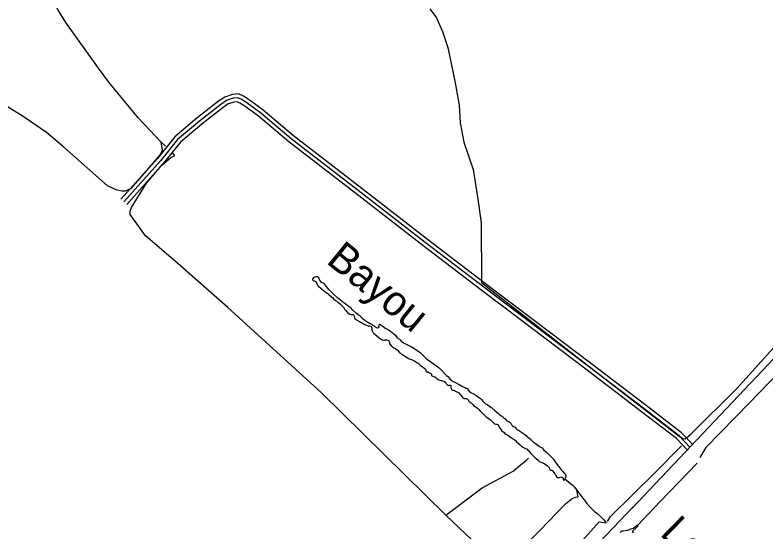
# Model space of a CAD drawing. Extents: x 3161665 to 3199565, y 885729 to 911164.
# Drawn here: x 3166281 to 3169197, y 904720 to 906728 of the extents above; entities that cross this region are included whole.
import ezdxf

# ---------------------------------------------------------------- set-up
doc = ezdxf.new("R2010")
doc.units = 0
for name, color, linetype in [('V-RIVR-IDEN', 7, 'Continuous'), ('V-ROAD-CNTR', 7, 'Continuous'), ('V-TOPO-SHOR', 7, 'Continuous')]:
    doc.layers.add(name, color=color, linetype=linetype)

msp = doc.modelspace()

# ---------------------------------------------------------------- linework, layer by layer
at = {"layer": 'V-ROAD-CNTR'}
for points in [[(3170298.7, 906515.6), (3169343.1, 905515.1), (3168677.2, 904811.3)], [(3167186.6, 906400.7), (3167169.1, 906412.2), (3167149.6, 906421.2), (3167126, 906419.3), (3167095.8, 906409.3), (3167081.9, 906399.9)], [(3167081.9, 906399.9), (3167071.4, 906392.6), (3166987.8, 906327), (3166901.8, 906255.1), (3166834.3, 906171), (3166692.6, 906012.1)], [(3168902.4, 905049.3), (3168859.9, 905093.7), (3168723.7, 905199.1), (3168507.4, 905363.7), (3168188, 905605), (3167873.6, 905844), (3167614.2, 906046.6), (3167353.7, 906246.4), (3167236.2, 906347), (3167187, 906382.4), (3167161.8, 906399.1), (3167146.9, 906406), (3167129, 906404.5), (3167102.5, 906395.8), (3167080.2, 906380.5), (3166997.3, 906315.3), (3166912.5, 906244.5), (3166845.8, 906161.3), (3166703.8, 906002.1)], [(3167167.5, 906377.3), (3167154.5, 906385.9), (3167144.2, 906390.7), (3167132, 906389.7), (3167109.2, 906382.2), (3167098, 906374.5)], [(3168108.6, 905684.2), (3167882.7, 905855.9), (3167623.4, 906058.4), (3167363.2, 906258.1), (3167245.5, 906358.8), (3167195.5, 906394.8), (3167188.5, 906399.4)], [(3167098, 906374.5), (3167089.1, 906368.4), (3167006.7, 906303.7), (3166923.3, 906234), (3166857.2, 906151.6), (3166715, 905992.1)], [(3168090.6, 905660.2), (3167864.4, 905832.1), (3167605.1, 906034.7), (3167344.3, 906234.7), (3167227, 906335.2), (3167178.5, 906370.1), (3167167.5, 906377.3)], [(3168891.6, 905038.9), (3168849.8, 905082.5), (3168714.6, 905187.2), (3168498.3, 905351.7), (3168178.9, 905593), (3168090.6, 905660.2)], [(3168913.3, 905059.7), (3168869.9, 905104.9), (3168732.8, 905211), (3168516.4, 905375.6), (3168197.1, 905616.9), (3168108.6, 905684.2)], [(3168682.8, 904817.2), (3168682.1, 904817.3), (3168500.2, 904627.3), (3168260.8, 904368.7), (3167998.1, 904096.6), (3167913.2, 904008.1), (3167816, 903915.2), (3167746.2, 903847.5), (3167631.8, 903748), (3167456.1, 903609.1), (3167355.1, 903531.9), (3167229.6, 903443.7), (3167105.2, 903362.7), (3166973.6, 903283.3), (3166847.9, 903211.6), (3166848.1, 903211.9), (3166676.1, 903125.4), (3166497, 903041.3), (3166200.2, 902917.8), (3166006.1, 902838.5), (3165919.5, 902802.7)]]:
    msp.add_lwpolyline(points, dxfattribs=at)
at = {"layer": 'V-TOPO-SHOR'}
for points in [[(3166847.9, 906234.9), (3166760.3, 906327.2), (3166645, 906466.6), (3166605.5, 906521.3), (3166478.4, 906698.3), (3166447.5, 906748.6), (3166400.6, 906843), (3166306.9, 907093.7), (3166238.8, 907250.1)], [(3167891.8, 906751.9), (3167918.5, 906716.5), (3167940.8, 906664), (3167962.1, 906601.8), (3167990.7, 906463.7), (3168005.5, 906378), (3168009.6, 906309.5), (3168024.5, 906234.5), (3168060.6, 906127.4), (3168078.6, 906012.8), (3168091.2, 905920.7), (3168092.9, 905689.4), (3168452, 905408.1), (3168860.2, 905092.5), (3168876.3, 905082.8), (3168883.8, 905081.7), (3168906.3, 905099.8), (3169084.4, 905277.2), (3169274.4, 905487.7)], [(3166866, 906218.8), (3166847.9, 906234.9), (3166852.1, 906202.8), (3166846.7, 906186.8), (3166809.1, 906142.9), (3166729.7, 906053.2), (3166709.3, 906043.6), (3166696.5, 906043.6), (3166674, 906049), (3166639.8, 906064.1), (3166471, 906214.4), (3166403.6, 906271.2), (3166309.6, 906335.7), (3166153.5, 906430.2), (3166056.2, 906495.8), (3165966.4, 906555.9), (3165923.6, 906588.1)], [(3170196.9, 906325), (3170037, 906157.3), (3169780.6, 905889.1), (3169471.5, 905570.7), (3169134.6, 905222.5), (3168964, 905048.3), (3168940.4, 905009.8)], [(3167953.8, 904785), (3167472, 905260.4), (3167107.7, 905592), (3166904.7, 905770.2), (3166788.2, 905870), (3166756.2, 905915), (3166728.4, 905953.6), (3166728.4, 905966.5), (3166733.8, 905980.4), (3166791.8, 906074.5), (3166849.8, 906142.9), (3166886.3, 906174.9), (3166902.3, 906182.4), (3166891.7, 906195.2)], [(3167701.9, 905523.9), (3167699.8, 905525.2), (3167696.4, 905526.2), (3167693.7, 905524.4), (3167693.1, 905520.7), (3167693.9, 905516.1), (3167692.4, 905512.6), (3167688.8, 905511.2), (3167685.1, 905513.1), (3167677.8, 905518.4), (3167674.8, 905520.2), (3167672, 905522.5), (3167669.1, 905524.3), (3167661.8, 905528.2), (3167658, 905529.7), (3167651.7, 905533.2), (3167648.3, 905535.4), (3167644.6, 905537.5), (3167641, 905539.9), (3167631.1, 905548.9), (3167626.4, 905552.6), (3167621, 905557.5), (3167612.9, 905564.3), (3167610.7, 905566.5), (3167606.6, 905570.2), (3167592.3, 905582.4), (3167584.8, 905590), (3167579.5, 905594.3), (3167575.7, 905597.4), (3167569, 905602.3), (3167566.2, 905604.7), (3167558.7, 905609.9), (3167554.6, 905613.1), (3167550, 905616.2), (3167545.9, 905618.9), (3167539.7, 905624), (3167535.4, 905628.3), (3167532, 905631.1), (3167518.8, 905642.8), (3167510.8, 905651.4), (3167503.1, 905658.9), (3167500.1, 905662.2), (3167494.4, 905668.7), (3167487.4, 905678.5), (3167482.1, 905683.4), (3167477.8, 905686.1), (3167471.6, 905689.4), (3167467.1, 905694.1), (3167464.5, 905698.3), (3167462.5, 905703.4), (3167461.1, 905707.5), (3167458.5, 905710.2), (3167455.6, 905711.2), (3167451.6, 905711.4), (3167445.5, 905710), (3167439.2, 905705.2), (3167436.5, 905701.7), (3167436.1, 905698.7), (3167438.5, 905696.9), (3167446.4, 905694), (3167449.6, 905691.3), (3167452.9, 905685.2), (3167455.1, 905681.5), (3167456.7, 905677.9), (3167458.7, 905675), (3167462.7, 905671.5), (3167469, 905667.2), (3167472, 905664.6), (3167479.5, 905657.2), (3167483, 905654.8), (3167485.8, 905652.3), (3167496.1, 905645.6), (3167500.2, 905642.5), (3167510.7, 905633.5), (3167514.9, 905629.4), (3167517.9, 905625.9), (3167525.8, 905618.8), (3167530.5, 905615.9), (3167534.1, 905613.2), (3167538, 905610.8), (3167545.4, 905604.2), (3167550.7, 905599.3), (3167556.4, 905592.6), (3167561.4, 905585.3), (3167563.4, 905582.6), (3167567.2, 905579.1), (3167574.3, 905570.4), (3167577.3, 905567.9), (3167581.6, 905565.4), (3167586.9, 905564.2), (3167590.3, 905565.2), (3167594.2, 905564.6), (3167597.4, 905561.9), (3167598.8, 905558.8), (3167599.2, 905551.1), (3167601, 905548.7), (3167607.9, 905543.6), (3167618.6, 905537.8), (3167625.3, 905533.5), (3167634.2, 905528.2), (3167642.5, 905524.1)], [(3167642.5, 905524.1), (3167646.8, 905522.6), (3167652.4, 905521.2), (3167657.5, 905520.7), (3167664.2, 905519.7), (3167666.8, 905513.2), (3167667.4, 905509.5), (3167667.2, 905505.2), (3167668, 905501), (3167669.2, 905498.1), (3167672, 905493.2), (3167674.6, 905491), (3167678.7, 905488.7), (3167686.6, 905482), (3167694.7, 905475.8), (3167700.5, 905470.3), (3167703.8, 905467.7), (3167707.4, 905465.6), (3167711.9, 905464.6), (3167715.7, 905464.3), (3167718.6, 905465.7), (3167721.8, 905466.5), (3167724.9, 905466.1), (3167728.7, 905465.3), (3167731.4, 905463.4), (3167733.8, 905460.4), (3167736, 905452.6), (3167741.6, 905443.5), (3167744, 905440.4), (3167746.7, 905438.4), (3167752.1, 905435.3), (3167755.2, 905434.3), (3167759, 905432.2), (3167766.3, 905425.9), (3167774.8, 905416.7), (3167777.8, 905414.4), (3167782.7, 905411.1), (3167787.5, 905408.3), (3167803.5, 905397.2), (3167812.4, 905392.5), (3167823.2, 905388), (3167830.1, 905385.7), (3167837.6, 905381.4), (3167841.2, 905378.5), (3167846.5, 905375), (3167851.7, 905370.7), (3167854.3, 905368.3), (3167863.9, 905361.7), (3167867.3, 905359.1), (3167872.8, 905355.4), (3167875, 905352.9), (3167876.6, 905348.9), (3167876.8, 905345.6), (3167879.8, 905341.7), (3167882.8, 905341.3), (3167886.9, 905340.3), (3167891.1, 905338.2), (3167895.8, 905335.1), (3167898, 905332.9), (3167898.8, 905329), (3167900.4, 905326), (3167903.7, 905324.5), (3167907.1, 905323.9), (3167911.6, 905322.3), (3167916.6, 905319.2), (3167919.9, 905316.1), (3167923.7, 905313.1), (3167927.2, 905311.4), (3167937.9, 905308.3), (3167945.8, 905305.4), (3167948.6, 905303.8), (3167952.1, 905300.9), (3167954.1, 905298.7), (3167956.9, 905294), (3167959.3, 905291.3), (3167964, 905289.1), (3167966.9, 905290.1), (3167971.3, 905290.6), (3167974, 905288.8), (3167973.9, 905284.5), (3167973.7, 905281.3), (3167974.5, 905277.2), (3167977.3, 905272.3), (3167980.4, 905270.9), (3167984, 905270.7), (3167987.7, 905269), (3167991.3, 905266.4), (3168004.1, 905260.2), (3168007.9, 905257.1), (3168010.1, 905254.5), (3168017.2, 905245.1), (3168020.8, 905241.8), (3168025.3, 905238.7), (3168033.6, 905237.9), (3168036.6, 905236.9), (3168041.1, 905233), (3168042.9, 905229.3), (3168045.9, 905225), (3168049, 905223), (3168053, 905220.9), (3168055.8, 905218.5)], [(3167701.9, 905523.9), (3167708, 905519.6), (3167710.8, 905518), (3167715.7, 905513.5), (3167718, 905512.7)], [(3167718, 905512.7), (3167721.5, 905510), (3167729, 905506.5), (3167733.8, 905503.6), (3167739.3, 905499.6), (3167745.3, 905494.6), (3167748.2, 905492), (3167751, 905490.1), (3167756.9, 905485), (3167759.7, 905481.8), (3167765.5, 905473.6), (3167773.8, 905469.3), (3167777.1, 905466), (3167781.1, 905460.9), (3167784.3, 905457.9), (3167789.8, 905454.6), (3167792.7, 905453.5), (3167795.5, 905451.7), (3167804.8, 905446.6), (3167818.8, 905440.2), (3167821.6, 905438.6), (3167830.7, 905432.4), (3167834, 905430.8), (3167842.3, 905425.2), (3167849.3, 905420.3), (3167856, 905415.4), (3167860.1, 905411.9), (3167868.3, 905403), (3167880.5, 905391.7), (3167899.1, 905379), (3167907, 905373.1), (3167914.7, 905367.7), (3167922.6, 905361.4), (3167929.2, 905356.5), (3167932.5, 905353.8), (3167941.6, 905345.1), (3167951.9, 905333.2), (3167957.3, 905328.1), (3167961.6, 905323.6), (3167968, 905316.3), (3167979.3, 905307.5), (3167983, 905305), (3167989.3, 905302.1), (3167991.9, 905300.5), (3168006.3, 905292.3), (3168019, 905285.5), (3168022.5, 905283.5), (3168028.2, 905280.6), (3168032, 905278.9), (3168035.2, 905277.9), (3168038.1, 905276.1), (3168041.3, 905272), (3168045.3, 905266.5), (3168050, 905263), (3168053.4, 905260.1), (3168056.7, 905258.5), (3168065, 905254.8), (3168068.8, 905252.3), (3168075.9, 905247.2), (3168080.8, 905243.9), (3168088.5, 905238.2), (3168093.9, 905233.3), (3168096.7, 905229.8), (3168102.8, 905223.1), (3168105.4, 905220.6), (3168108.5, 905218.2), (3168114.5, 905214.5), (3168119.4, 905211.6), (3168122.8, 905209.4), (3168130.1, 905203.8), (3168132.9, 905201.6), (3168145.7, 905190.1), (3168158.8, 905179.7), (3168162.7, 905176.2), (3168169.1, 905171.5), (3168172.8, 905169.3), (3168176.6, 905166.4), (3168180.1, 905162.9), (3168184.3, 905159.2), (3168191.6, 905152.1), (3168194.6, 905150.2), (3168197.5, 905149.2), (3168200.5, 905147.6), (3168203.7, 905145.3), (3168206.2, 905142.3), (3168208.8, 905137.4), (3168210.6, 905134.7), (3168213.4, 905132.3), (3168217.5, 905130), (3168224.6, 905126.5), (3168226.2, 905123), (3168228.6, 905120), (3168234.7, 905115.9), (3168240.7, 905112.2), (3168243.8, 905110.6), (3168246.6, 905108.1), (3168249, 905106.3), (3168253.3, 905103.8), (3168257.3, 905100.7), (3168264.8, 905095.4), (3168270.1, 905090.1)], [(3168055.8, 905218.5), (3168058.7, 905214.8), (3168061.5, 905211.7), (3168068.4, 905206.8), (3168077.1, 905200.9), (3168079.7, 905198.4), (3168083.1, 905194.7), (3168087.6, 905189.6), (3168090, 905187.4), (3168092.4, 905184.7), (3168101.5, 905176.6), (3168109.4, 905168), (3168118.1, 905161.8), (3168128.4, 905153.7), (3168138.9, 905143.6), (3168143.4, 905140), (3168148, 905138.3), (3168152.1, 905138.3), (3168155.7, 905137.7), (3168157.6, 905135.2), (3168158.8, 905132.2), (3168161.2, 905128.7), (3168164.4, 905123), (3168169, 905116.1), (3168171.7, 905112.8), (3168180.2, 905105.8), (3168183.4, 905102.8), (3168187.4, 905099.9), (3168190.9, 905097.9), (3168194.3, 905096.4), (3168198, 905094.4), (3168204.6, 905090.1), (3168223.5, 905076.1), (3168226.1, 905073.7), (3168228.9, 905070.6), (3168235.8, 905064.3), (3168243.1, 905057.9), (3168246.7, 905054.3), (3168253.2, 905049.2), (3168263.9, 905044.8), (3168269.8, 905041.1), (3168273.2, 905038.1), (3168276.3, 905034.8), (3168278.7, 905031.7), (3168284.1, 905024.2), (3168288, 905021.3), (3168291.4, 905018.5), (3168301.7, 905008.5), (3168304.7, 905005.8), (3168312.2, 904998.2), (3168314.8, 904995.8), (3168317.3, 904993.9), (3168320.1, 904992.5), (3168323.5, 904991.5), (3168330.8, 904988.8), (3168334.1, 904987.2), (3168344, 904981.2), (3168349.3, 904976.9), (3168352.7, 904973.2), (3168354.9, 904969.8), (3168356.9, 904965.7), (3168358.7, 904962.6), (3168362, 904960.4), (3168365.4, 904960.4), (3168368.7, 904957.9), (3168378.1, 904946.3), (3168380, 904943.6), (3168384.2, 904934.7), (3168387.4, 904931.4), (3168390.9, 904930.4), (3168394.9, 904931.6), (3168401, 904934), (3168404.3, 904932.9), (3168407.3, 904931.5), (3168409.3, 904928.6), (3168409.7, 904925), (3168411.7, 904921.7), (3168414.8, 904922.7), (3168416.6, 904926.6)], [(3168270.1, 905090.1), (3168272.9, 905088.3), (3168281.4, 905081.3), (3168295.5, 905067.4), (3168298, 905065.6), (3168306.1, 905060.4), (3168318.4, 905052), (3168323.3, 905049.8), (3168328.1, 905046.9), (3168332, 905041.8), (3168335.2, 905038.3), (3168339.4, 905034.3), (3168345.3, 905029.5), (3168349.7, 905025.7), (3168359.8, 905015.2), (3168365.9, 905009.5), (3168372.2, 905003), (3168375.8, 904996.7), (3168379, 904991.8), (3168389.7, 904978.7), (3168393.1, 904974), (3168396, 904970.6), (3168403.8, 904959.5), (3168408.3, 904954.2), (3168413.7, 904948.7), (3168418.4, 904942.8), (3168419.8, 904939.1), (3168419.9, 904935.5), (3168419.1, 904931.4), (3168416.6, 904926.6)], [(3168582.2, 904760.1), (3168594, 904780.4), (3168766.8, 904950.3), (3168869.8, 905055)], [(3167953.8, 904785), (3168095.4, 904891.8), (3168215.4, 904955.8), (3168234.7, 904972.8), (3168256.2, 904989.9), (3168266.9, 904998.5), (3168275.5, 905007)], [(3168930.7, 904987.4), (3168786.9, 904837.8), (3168699.3, 904746.2)], [(3168416.6, 904926.6), (3168446.2, 904901.4), (3168452, 904895.3), (3168463.1, 904882.6), (3168502, 904830.4), (3168513.9, 904817.7), (3168531.7, 904800), (3168540, 904793), (3168553, 904781.8), (3168567.7, 904767.1), (3168577.4, 904755.4)], [(3167953.8, 904785), (3168134.4, 904614.4), (3168161.1, 904602.6), (3168181.5, 904603.6), (3168192.2, 904610), (3168238.3, 904643.1), (3168318.8, 904725.3), (3168418.6, 904829), (3168444.3, 904850.3), (3168458.2, 904855.7), (3168467.9, 904856.7), (3168463.1, 904882.6)], [(3168143.3, 904296.4), (3168261.4, 904450.3), (3168440.6, 904637.3), (3168550.1, 904759.1), (3168577.4, 904755.4)], [(3168682.9, 904716.2), (3168679.9, 904720.9), (3168680.1, 904724.1), (3168682.4, 904726.6), (3168686.5, 904730.4), (3168689.1, 904732.4), (3168692.4, 904735.2), (3168694.8, 904737.7), (3168698.7, 904741.1), (3168701.4, 904743.9), (3168699.3, 904746.2), (3168695.3, 904744.8), (3168692.6, 904742.8), (3168690.4, 904740.5), (3168684.4, 904735.5), (3168681.8, 904733.9), (3168671.6, 904730.5), (3168664.1, 904727.3), (3168659.8, 904725.9), (3168656.8, 904725.3), (3168644.4, 904723.3), (3168637.7, 904722.9), (3168634.6, 904722.2), (3168631.7, 904718.1)]]:
    msp.add_lwpolyline(points, dxfattribs=at)

# ---------------------------------------------------------------- texts
at = {"layer": 'V-RIVR-IDEN'}
for s, rotation, p in [('Bayou', 320.8264, (3167485.8, 905767.1)), ('Lettsworth', 315.6367, (3168781.9, 904710.3))]:
    msp.add_text(s, height=116, rotation=rotation, dxfattribs=at).set_placement(p)

doc.saveas('drawing.dxf')
